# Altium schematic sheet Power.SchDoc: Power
size A4; DocumentNumber: MB1165; Revision: C.1; SheetNumber: 3; SheetTotal: 17; Project: STM32469I-EVAL
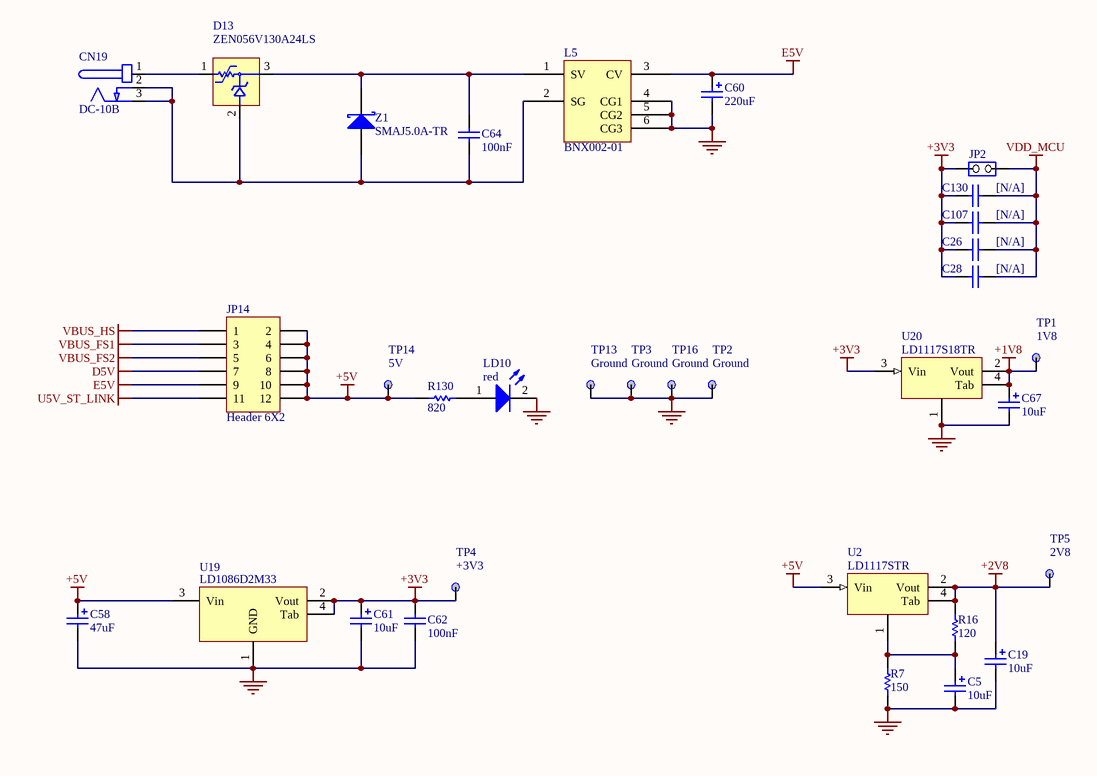
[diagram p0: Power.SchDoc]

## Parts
C5  10uF  [TAN-A]
C19  10uF  [TAN-A]
C26  [N/A]  [0603C]
C28  [N/A]  [0603C]
C58  47uF  [CAE_5R3X5R3_H5R4]
C60  220uF  [c310m-6]
C61  10uF  [TAN-A]
C62  100nF  [0603C]
C64  100nF  [0603C]
C67  10uF  [TAN-A]
C107  [N/A]  [0603C]
C130  [N/A]  [0603C]
CN19  DC-10B  [PWR_JACK_DC10]
D13  ZEN056V130A24LS  [TYCO_ZEN056V130A24LS]
JP2  (no value)  [SIP2]
JP14  Header 6X2  [HDR_2X6_2R54]
L5  BNX002-01  [BNX001]
LD10  red  [0603D]
R7  150  [0603R]
R16  120  [0603R]
R130  820  [0603R]
TP1  1V8  [TP]
TP2  Ground  [TP]
TP3  Ground  [TP]
TP4  +3V3  [TP]
TP5  2V8  [TP]
TP13  Ground  [TP]
TP14  5V  [TP]
TP16  Ground  [TP]
U2  LD1117STR  [SOT-223]
U19  LD1086D2M33  [TO263-3]
U20  LD1117S18TR  [SOT-223]
Z1  SMAJ5.0A-TR  [sma]

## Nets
+1V8: C67.1 TP1.1 U20.2(Vout) U20.4(Tab)
+2V8: C19.1 R16.1 TP5.1 U2.2(Vout) U2.4(Tab)
+3V3: C26.1 C28.1 C61.1 C62.1 C107.1 C130.1 JP2.1(COMMON) TP4.1 U19.2(Vout) U19.4(Tab) U20.3(Vin)
+5V: C58.1 JP14.2 JP14.4 JP14.6 JP14.8 JP14.10 JP14.12 R130.2 TP14.1 U2.3(Vin) U19.3(Vin)
D5V: JP14.7
E5V: C60.1 JP14.9 L5.3(CV)
GND: C5.2 C19.2 C58.2 C60.2 C61.2 C62.2 C67.2 L5.4(CG1) L5.5(CG2) L5.6(CG3) LD10.2(K) R7.2 TP2.1 TP3.1 TP13.1 TP16.1 U19.1(GND) U20.1
U5V_ST_LINK: JP14.11
VBUS_FS1: JP14.3
VBUS_FS2: JP14.5
VBUS_HS: JP14.1
VDD_MCU: C26.2 C28.2 C107.2 C130.2 JP2.2(NO)
NetC5_1: C5.1 R7.1 R16.2 U2.1
NetC64_1: C64.1 D13.3 L5.1(SV) Z1.2(K)
NetC64_2: C64.2 CN19.2(GND) CN19.3(GND) D13.2 L5.2(SG) Z1.1(A)
NetCN19_1: CN19.1(+) D13.1
NetLD10_1: LD10.1(A) R130.1

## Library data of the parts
C5 C19 C61 C67 = Cap Pol1: Polarized Capacitor (Radial)
C26 C28 C62 C107 C130 = Cap: Capacitor; Value: 10nF
C58 = Cap Pol1: Polarized Capacitor (Radial); Value: 10uF
C60 = Cap Pol1: Polarized Capacitor (Radial); Value: 47uF
C64 = CAP: Capacitor; Value: 100pF
CN19 = PJ202A
JP2 = JP2
JP14 = Header 6X2: Header, 6-Pin, Dual row
L5 = BNX002
LD10 = LED2: Typical RED, GREEN, YELLOW, AMBER GaAs LED
R7 R16 R130 = res1: Resistor; Value: 1K
TP1-TP5 TP13 TP14 TP16 = TP
U2 U20 = LD1117
U19 = VOLTREG1
Z1 = D Schottky: Schottky Diode; Code - JEDEC: DO-214-AA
